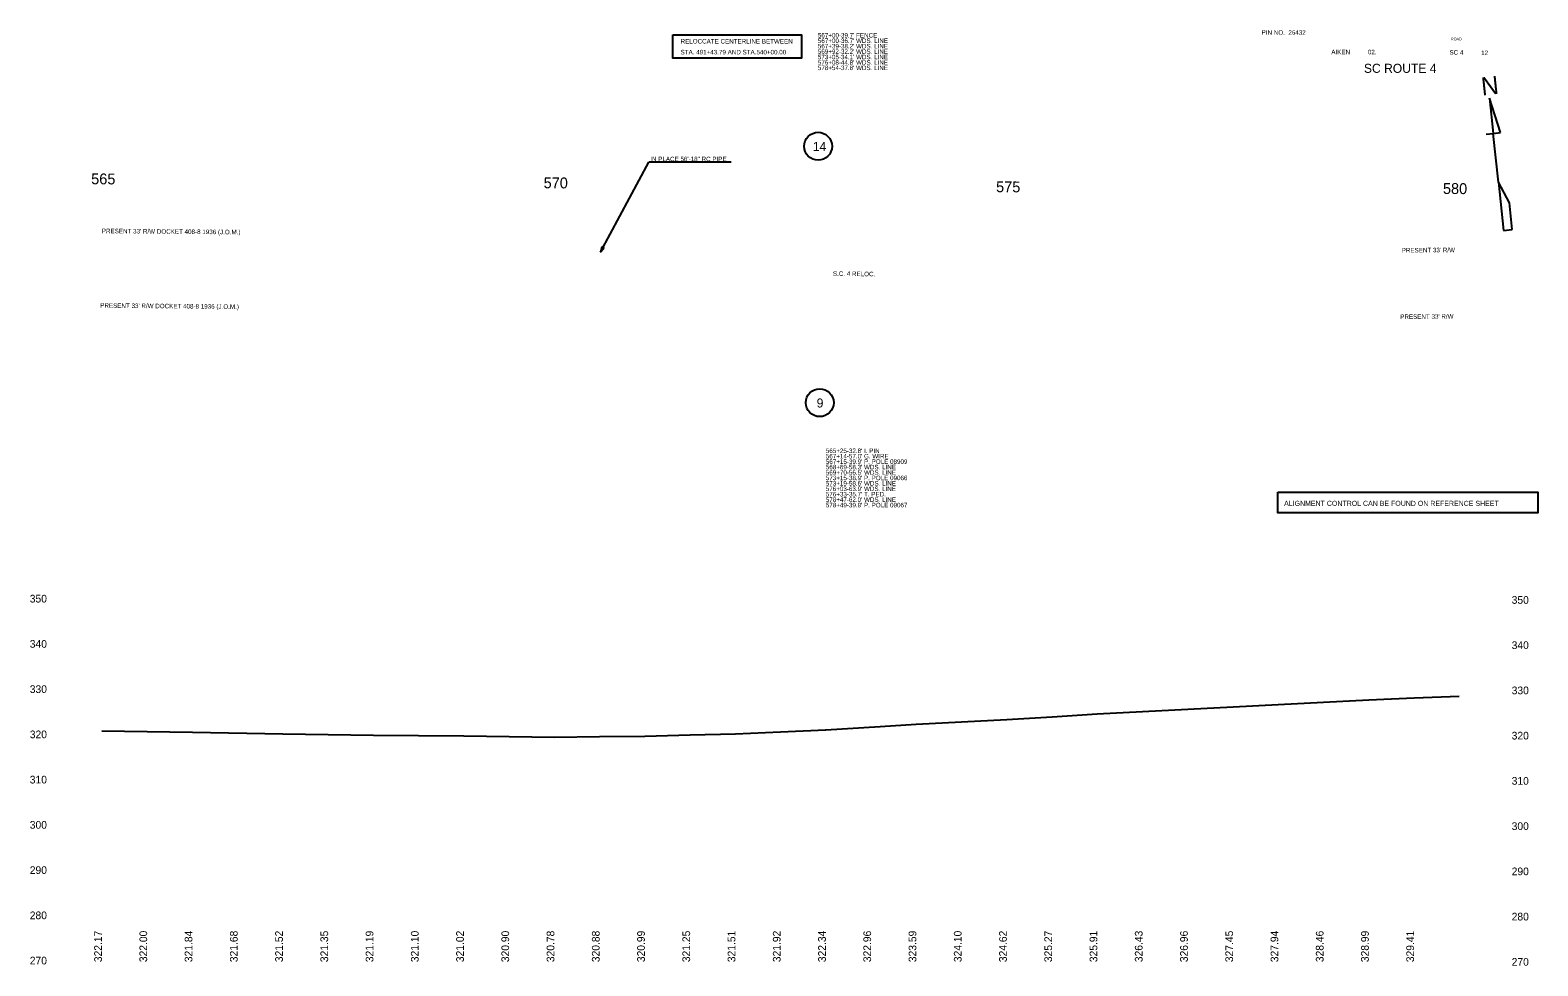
# Model space of a CAD drawing. Extents: x 48556 to 51363, y 45290 to 53458.
# Drawn here: x 49109 to 50775, y 52424 to 53458 of the extents above; entities that cross this region are included whole.
import ezdxf

# ---------------------------------------------------------------- set-up
doc = ezdxf.new("R2010")
doc.units = 0
for name, color, linetype in [('Level 1', 7, 'Continuous'), ('Level 12', 7, 'Continuous'), ('Level 19', 7, 'Continuous'), ('Level 2', 7, 'Continuous'), ('Level 24', 7, 'Continuous'), ('Level 25', 7, 'Continuous'), ('Level 39', 7, 'Continuous'), ('Level 40', 7, 'Continuous'), ('Level 42', 7, 'Continuous'), ('Level 43', 7, 'Continuous'), ('Level 6', 7, 'Continuous')]:
    doc.layers.add(name, color=color, linetype=linetype)

msp = doc.modelspace()

# ---------------------------------------------------------------- linework, layer by layer
at = {"layer": 'Level 12'}
for centre in [(49979.4, 53329.7), (49981.2, 53046.2)]:
    msp.add_circle(centre, 15.4, dxfattribs=at)
at = {"layer": 'Level 2'}
for p, q in [((50733.3, 53344.7), (50721.4, 53382.9)), ((50721.4, 53382.9), (50721.4, 53382.9)), ((50721.4, 53382.9), (50725.5, 53343.9)), ((50717.7, 53343.1), (50725.5, 53343.9)), ((50725.5, 53343.9), (50733.3, 53344.7)), ((50731.1, 53289.8), (50725.5, 53343.9)), ((50733.3, 53344.7), (50733.2, 53345.2)), ((50743.4, 53267), (50731.1, 53289.8)), ((50731.1, 53289.8), (50736.7, 53236.7)), ((50746.5, 53237.7), (50743.4, 53267.2)), ((50743.4, 53267.2), (50743.4, 53267)), ((50736.7, 53236.7), (50746.5, 53237.7))]:
    msp.add_line(p, q, dxfattribs=at)
at = {"layer": 'Level 24'}
for p, q in [((49740.5, 53218.5), (49739, 53212.5)), ((49739, 53212.5), (49743.1, 53217)), ((49743.1, 53217), (49740.5, 53218.5))]:
    msp.add_line(p, q, dxfattribs=at)
at = {"layer": 'Level 25'}
msp.add_lwpolyline([(50487.4, 52947.3), (50774.7, 52947.3), (50774.7, 52924.6), (50487.4, 52924.6)], close=True, dxfattribs=at)
at = {"layer": 'Level 40'}
msp.add_lwpolyline([(49187.9, 52683.7), (49237.9, 52682.9), (49287.9, 52682.1), (49387.9, 52680.4), (49437.9, 52679.6), (49487.9, 52678.8), (49537.9, 52678.4), (49587.9, 52678), (49687.9, 52676.7), (49737.9, 52677.3), (49787.9, 52677.8), (49837.9, 52679.1), (49887.9, 52680.4), (49937.9, 52682.5), (49987.9, 52684.5), (49988, 52684.6), (50047.9, 52688.3), (50087.9, 52690.8), (50137.9, 52693.4), (50187.9, 52696), (50237.9, 52699.2), (50287.9, 52702.4), (50387.9, 52707.7), (50437.9, 52710.1), (50487.9, 52712.6), (50537.9, 52715.2), (50587.9, 52717.8), (50637.9, 52719.9), (50687.9, 52722)], dxfattribs=at)
at = {"layer": 'Level 6'}
for p in [(49739, 53212.5), (49883.3, 53312.2)]:
    msp.add_line(p, (49792.3, 53312.2), dxfattribs=at)
msp.add_lwpolyline([(49818.8, 53452.7), (49960.9, 53452.7), (49960.9, 53427), (49818.8, 53427)], close=True, dxfattribs=at)

# ---------------------------------------------------------------- texts
at = {"layer": 'Level 1'}
for s, rotation, p in [("PRESENT 33' R/W DOCKET 408-8 1936 (J.O.M.)", 359.4944, (49187.8, 53233.6)), ("PRESENT 33' R/W", 0.4035, (50624.3, 53212.2)), ("PRESENT 33' R/W DOCKET 408-8 1936 (J.O.M.)", 359.4944, (49186.1, 53151.2)), ("PRESENT 33' R/W", 0.4035, (50622.7, 53138.7))]:
    msp.add_text(s, height=5, rotation=rotation, dxfattribs=at).set_placement(p)
at = {"layer": 'Level 12'}
for s, p in [('14', (49973.5, 53324.4)), ('9', (49977.8, 53040.9))]:
    msp.add_text(s, height=10, dxfattribs=at).set_placement(p)
at = {"layer": 'Level 19'}
for s, p in [('565', (49176, 53287.7)), ('570', (49676, 53283.3)), ('575', (50176, 53278.9)), ('580', (50669.8, 53277))]:
    msp.add_text(s, height=12, rotation=359.4944, dxfattribs=at).set_placement(p)
at = {"layer": 'Level 2'}
msp.add_text('N', height=20, rotation=6, dxfattribs=at).set_placement((50713.1, 53385.7))
at = {"layer": 'Level 24'}
for s, height, p in [("567+00-39.7' FENCE", 5, (49979.1, 53449.8)), ("567+00-36.7' WDS. LINE", 5, (49979.1, 53443.8)), ('PIN NO.  26432', 5, (50469.5, 53452.9)), ('ROAD', 3, (50678.7, 53446.7)), ("567+39-38.2' WDS. LINE", 5, (49979.1, 53437.8)), ("569+92-32.2' WDS. LINE", 5, (49979.1, 53431.8)), ('AIKEN', 5, (50546.5, 53431.3)), ('02.', 5, (50586.9, 53431.3)), ('SC 4', 5, (50677.1, 53430.9)), ('12', 5, (50712, 53430.4)), ("573+05-34.1' WDS. LINE", 5, (49979.1, 53425.8)), ("576+08-44.8' WDS. LINE", 5, (49979.1, 53419.8)), ("578+54-37.8' WDS. LINE", 5, (49979.1, 53413.8)), ('SC ROUTE 4', 10, (50582.5, 53410.8)), ("565+25-32.8' I. PIN", 5, (49987.9, 52990.6)), ("567+14-57.0' G. WIRE", 5, (49987.9, 52984.6)), ("567+15-39.9' P. POLE 08909", 5, (49987.9, 52978.6)), ("568+69-58.3' WDS. LINE", 5, (49987.9, 52972.6)), ("569+70-56.5' WDS. LINE", 5, (49987.9, 52966.6)), ("573+15-38.9' P. POLE 09066", 5, (49987.9, 52960.6)), ("573+19-58.6' WDS. LINE", 5, (49987.9, 52954.6)), ("576+03-63.9' WDS. LINE", 5, (49987.9, 52948.6)), ("576+33-35.7' T. PED.", 5, (49987.9, 52942.6)), ("578+47-62.0' WDS. LINE", 5, (49987.9, 52936.6)), ("578+49-39.9' P. POLE 09067", 5, (49987.9, 52930.6))]:
    msp.add_text(s, height=height, dxfattribs=at).set_placement(p)
at = {"layer": 'Level 25'}
msp.add_text('ALIGNMENT CONTROL CAN BE FOUND ON REFERENCE SHEET', height=5.6, dxfattribs=at).set_placement((50494.3, 52932.2))
at = {"layer": 'Level 39'}
msp.add_text('S.C. 4 RELOC.', height=5, rotation=359.2246, dxfattribs=at).set_placement((49995.7, 53186.5))
at = {"layer": 'Level 42'}
for s, p in [('350', (49108.2, 52825.4)), ('350', (50745.8, 52824)), ('340', (49108.2, 52775.4)), ('340', (50745.8, 52774)), ('330', (49108.2, 52725.4)), ('330', (50745.8, 52724)), ('320', (49108.2, 52675.4)), ('320', (50745.8, 52674)), ('310', (49108.2, 52625.4)), ('310', (50745.8, 52624)), ('300', (49108.2, 52575.4)), ('300', (50745.8, 52574)), ('290', (49108.2, 52525.4)), ('290', (50745.8, 52524)), ('280', (49108.2, 52475.4)), ('280', (50745.8, 52474)), ('270', (49108.2, 52425.4)), ('270', (50745.8, 52424))]:
    msp.add_text(s, height=8.5, dxfattribs=at).set_placement(p)
at = {"layer": 'Level 43'}
for s, p in [('322.17', (49187.9, 52427.9)), ('322.00', (49237.9, 52427.9)), ('321.84', (49287.9, 52427.9)), ('321.68', (49337.9, 52427.9)), ('321.52', (49387.9, 52427.9)), ('321.35', (49437.9, 52427.9)), ('321.19', (49487.9, 52427.9)), ('321.10', (49537.9, 52427.9)), ('321.02', (49587.9, 52427.9)), ('320.90', (49637.9, 52427.9)), ('320.78', (49687.9, 52427.9)), ('320.88', (49737.9, 52427.9)), ('320.99', (49787.9, 52427.9)), ('321.25', (49837.9, 52427.9)), ('321.51', (49887.9, 52427.9)), ('321.92', (49937.9, 52427.9)), ('322.34', (49987.9, 52427.9)), ('322.96', (50037.9, 52427.9)), ('323.59', (50087.9, 52427.9)), ('324.10', (50137.9, 52427.9)), ('324.62', (50187.9, 52427.9)), ('325.27', (50237.9, 52427.9)), ('325.91', (50287.9, 52427.9)), ('326.43', (50337.9, 52427.9)), ('326.96', (50387.9, 52427.9)), ('327.45', (50437.9, 52427.9)), ('327.94', (50487.9, 52427.9)), ('328.46', (50537.9, 52427.9)), ('328.99', (50587.9, 52427.9)), ('329.41', (50637.9, 52427.9))]:
    msp.add_text(s, height=8.5, rotation=90, dxfattribs=at).set_placement(p)
at = {"layer": 'Level 6'}
for s, p in [('STA. 491+43.79 AND STA.540+00.00', (49827.4, 53431.2)), ('RELOCCATE CENTERLINE BETWEEN', (49827.4, 53443.2)), ('IN PLACE 56\'-18" RC PIPE', (49793.9, 53313.1))]:
    msp.add_text(s, height=5, dxfattribs=at).set_placement(p)

doc.saveas('drawing.dxf')
